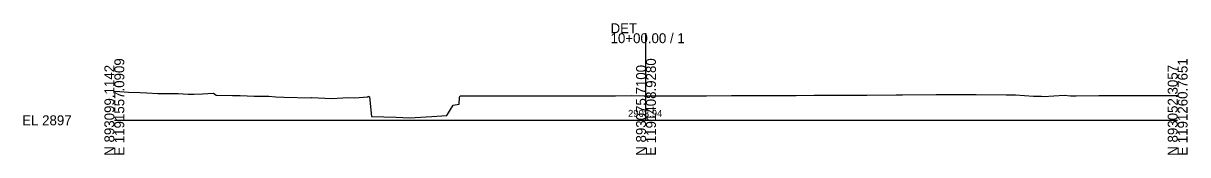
# Model space of a CAD drawing. Extents: x -26 to 1303, y -10 to 9537.
# Drawn here: x -25.7 to 302.8, y -9.7 to 27.3 of the extents above; entities that cross this region are included whole.
import ezdxf

# ---------------------------------------------------------------- set-up
doc = ezdxf.new("R2010")
doc.units = 0
for name, color, linetype in [('Default', 7, 'Continuous'), ('Exist Cross Section Cell', 7, 'Continuous'), ('Exist XS Center Line Elevation Label', 7, 'Continuous'), ('Exist XS Ground Line', 7, 'Continuous')]:
    doc.layers.add(name, color=color, linetype=linetype)

msp = doc.modelspace()

# ---------------------------------------------------------------- linework, layer by layer
at = {"layer": 'Exist Cross Section Cell'}
for p, q in [((150, 0), (150, 24.54)), ((0, 0), (150, 0)), ((150, 0), (300, 0))]:
    msp.add_line(p, q, dxfattribs=at)
at = {"layer": 'Exist XS Ground Line'}
for p, q in [((0, 8.18), (1.56, 8.08)), ((1.56, 8.08), (3.95, 7.95)), ((3.95, 7.95), (7.25, 7.82)), ((7.25, 7.82), (9.2, 7.7)), ((9.2, 7.7), (12.3, 7.6)), ((12.3, 7.6), (15.56, 7.54)), ((15.56, 7.54), (18.05, 7.52)), ((18.05, 7.52), (20.86, 7.38)), ((20.86, 7.38), (22.39, 7.39)), ((22.39, 7.39), (24.86, 7.45)), ((24.86, 7.45), (26.38, 7.51)), ((26.38, 7.51), (28.01, 7.61)), ((28.01, 7.61), (28.39, 7.35)), ((28.39, 7.35), (28.73, 7.09)), ((28.73, 7.09), (33.35, 7)), ((33.35, 7), (35.52, 6.97)), ((35.52, 6.97), (39.48, 6.79)), ((39.48, 6.79), (41.03, 6.77)), ((41.03, 6.77), (43.55, 6.77)), ((43.55, 6.77), (45.55, 6.6)), ((45.55, 6.6), (47.79, 6.51)), ((67.77, 6.36), (71.59, 6.63)), ((71.59, 6.63), (71.61, 6.76)), ((71.61, 6.76), (71.97, 6.57)), ((97.39, 6.52), (97.57, 6.92)), ((97.57, 6.92), (101.57, 6.9)), ((101.57, 6.9), (103.59, 6.9)), ((103.59, 6.9), (108.42, 6.91)), ((108.42, 6.91), (113.62, 6.9)), ((113.62, 6.9), (118.38, 6.91)), ((118.38, 6.91), (121.35, 6.91)), ((121.35, 6.91), (129.07, 6.92)), ((129.07, 6.92), (131.37, 6.92)), ((131.37, 6.92), (140.7, 6.94)), ((140.7, 6.94), (141.39, 6.94)), ((141.39, 6.94), (145.78, 6.95)), ((145.78, 6.95), (150, 6.94)), ((150, 6.94), (150.87, 6.94)), ((150.87, 6.94), (151.46, 6.94)), ((151.46, 6.94), (159.95, 6.93)), ((159.95, 6.93), (161.56, 6.91)), ((161.56, 6.91), (165.81, 6.93)), ((165.81, 6.93), (167.07, 6.93)), ((167.07, 6.93), (174.08, 6.95)), ((174.08, 6.95), (177.21, 6.97)), ((177.21, 6.97), (183.22, 6.99)), ((183.22, 6.99), (187.35, 7.01)), ((187.35, 7.01), (192.35, 7.02)), ((192.35, 7.02), (197.49, 7.05)), ((197.49, 7.05), (201.48, 7.06)), ((201.48, 7.06), (207.62, 7.09)), ((207.62, 7.09), (209.27, 7.1)), ((209.27, 7.1), (212.35, 7.12)), ((212.35, 7.12), (220.57, 7.18)), ((220.57, 7.18), (222.4, 7.19)), ((222.4, 7.19), (231.9, 7.25)), ((231.9, 7.25), (232.45, 7.25)), ((232.45, 7.25), (236.66, 7.28)), ((236.66, 7.28), (242.12, 7.25)), ((242.12, 7.25), (243.17, 7.24)), ((243.17, 7.24), (251.59, 7.2)), ((251.59, 7.2), (254.21, 7.19)), ((254.21, 7.19), (259.35, 6.8)), ((259.35, 6.8), (261.55, 6.76)), ((261.55, 6.76), (262.15, 6.74)), ((262.15, 6.74), (267.98, 7.11)), ((267.98, 7.11), (269.8, 6.94)), ((269.8, 6.94), (270.62, 6.93)), ((270.62, 6.93), (271.35, 6.94)), ((271.35, 6.94), (277.79, 6.98)), ((277.79, 6.98), (282.53, 6.98)), ((282.53, 6.98), (286.74, 7)), ((286.74, 7), (293.65, 7.01)), ((293.65, 7.01), (295.73, 7.01)), ((295.73, 7.01), (300, 7.02)), ((47.79, 6.51), (55.39, 6.33)), ((55.39, 6.33), (55.66, 6.46)), ((55.66, 6.46), (61.29, 6.17)), ((61.29, 6.17), (66.08, 6.4)), ((66.08, 6.4), (67.77, 6.36)), ((71.97, 6.57), (72.53, 1.1)), ((93.8, 1.36), (95.6, 4.24)), ((95.6, 4.24), (97.28, 4.57)), ((97.28, 4.57), (97.39, 6.52)), ((72.53, 1.1), (79.49, 0.86)), ((79.49, 0.86), (83.25, 0.68)), ((83.25, 0.68), (89.62, 1.1)), ((89.62, 1.1), (93.8, 1.36))]:
    msp.add_line(p, q, dxfattribs=at)

# ---------------------------------------------------------------- texts
at = {"layer": 'Default'}
msp.add_text('-', height=0.0001, dxfattribs=at).set_placement((0, 0))
at = {"layer": 'Exist Cross Section Cell'}
for s, p in [('DET', (140, 24.54)), ('10+00.00 / 1', (140, 21.74)), ('EL 2897', (-26, -1.4))]:
    msp.add_text(s, height=2.8, dxfattribs=at).set_placement(p)
for s, p in [('E 1191557.0909', (2.8, -10)), ('E 1191408.9280', (152.8, -10)), ('E 1191260.7651', (302.8, -10)), ('N 893099.1142', (0, -10)), ('N 893075.7100', (150, -10)), ('N 893052.3057', (300, -10))]:
    msp.add_text(s, height=2.8, rotation=90, dxfattribs=at).set_placement(p)
at = {"layer": 'Exist XS Center Line Elevation Label'}
msp.add_text('2903.94', height=2, dxfattribs=at).set_placement((144.93, 0.94))

doc.saveas('drawing.dxf')
